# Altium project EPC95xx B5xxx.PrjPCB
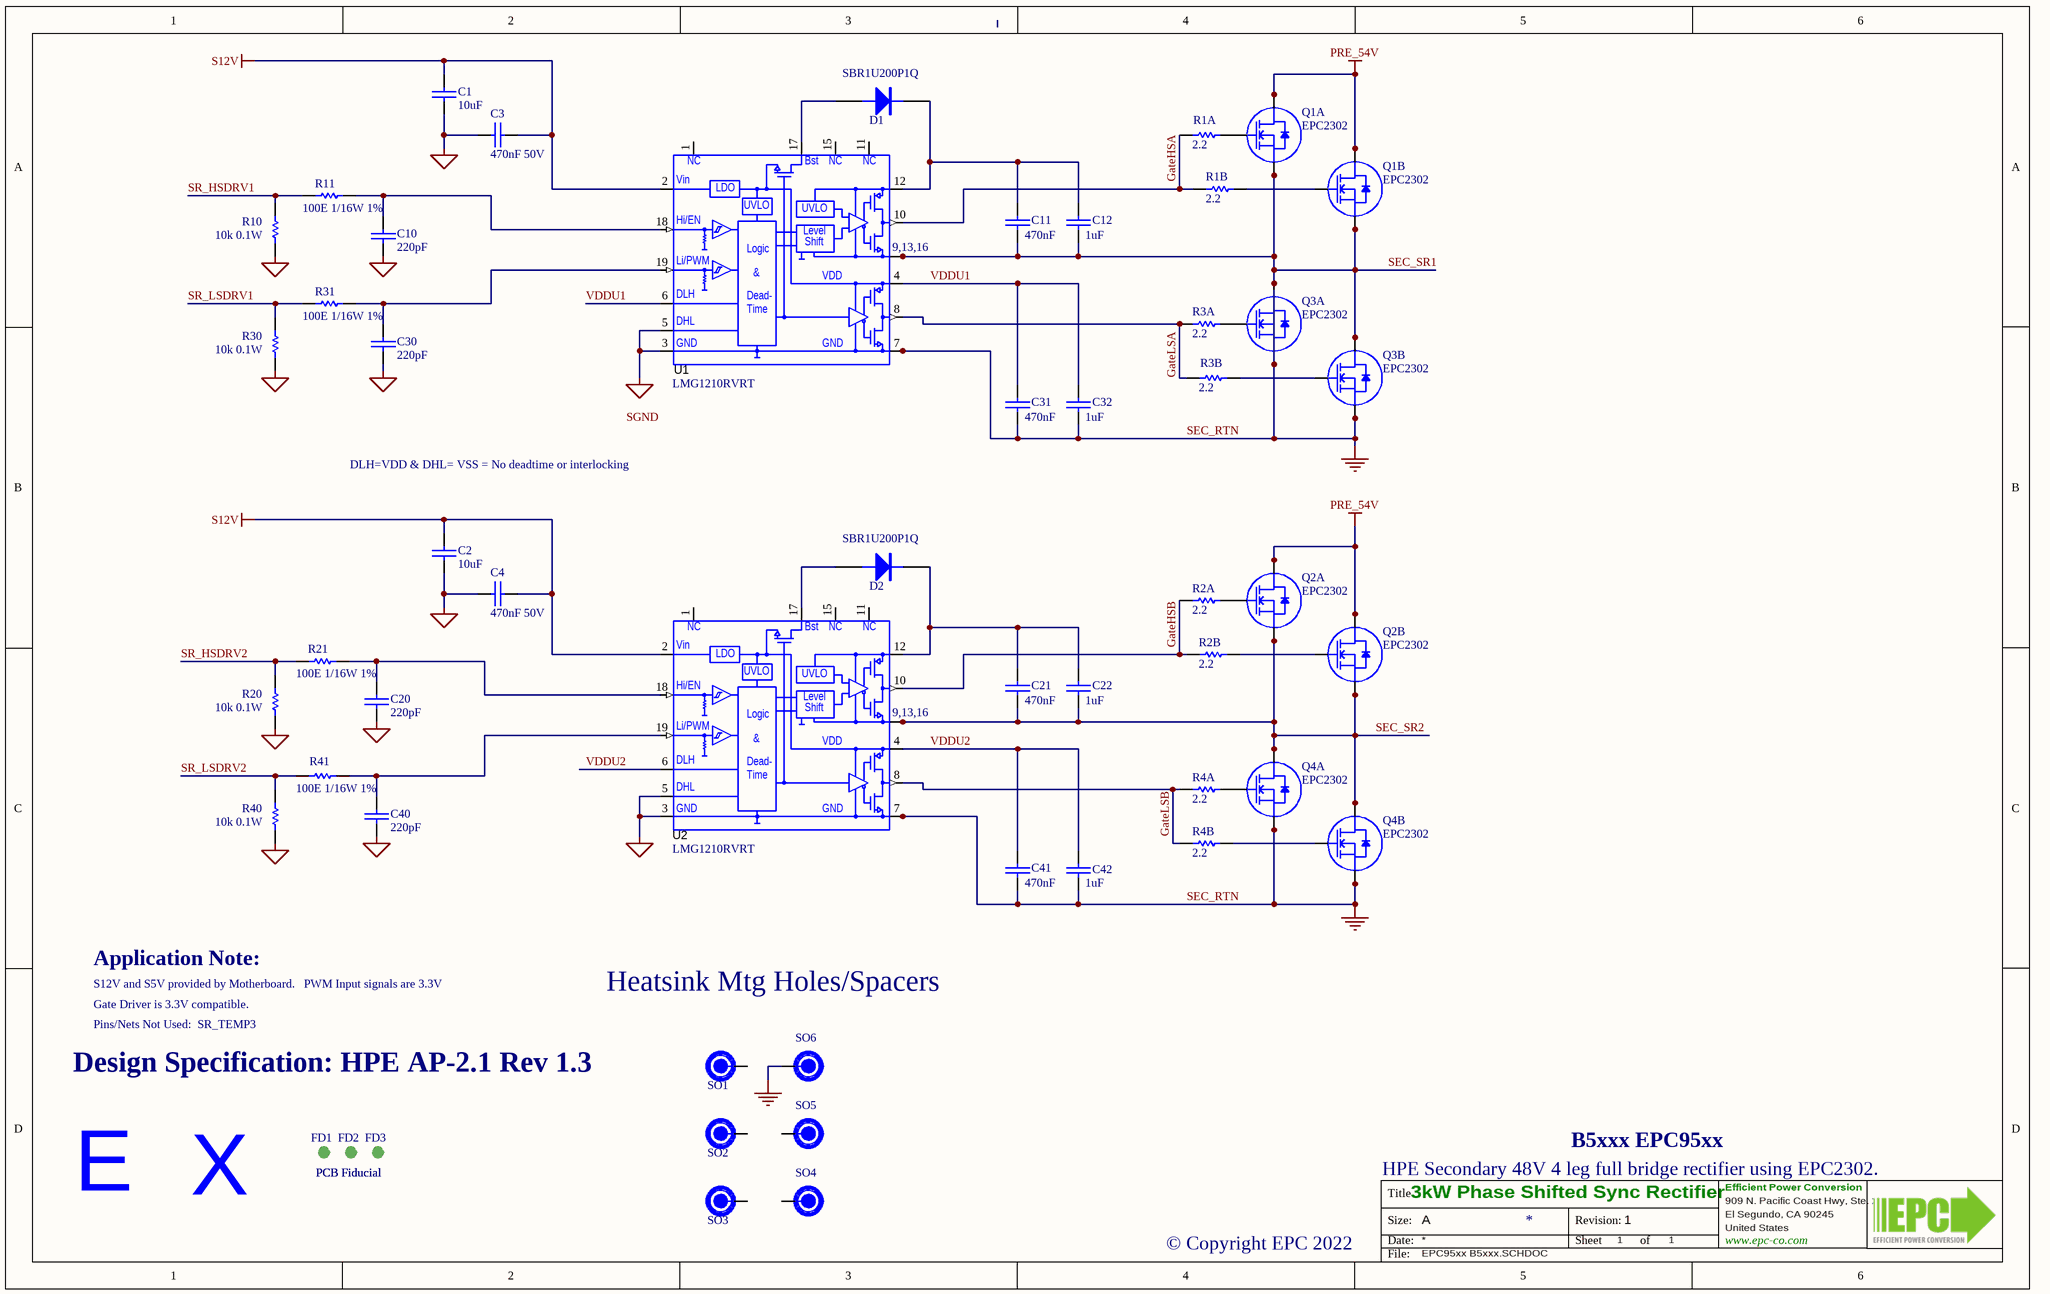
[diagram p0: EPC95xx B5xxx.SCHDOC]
1 sheet, 55 parts. Net scope: global (net labels, ports and power ports of the same name join across sheets).
Board file: EPC95xx B5xxx.PCBDOC

## Sheet EPC95xx B5xxx.SCHDOC: 3kW Phase Shifted Sync Rectifier
size B; Organization: Efficient Power Conversion; Address1: 909 N. Pacific Coast Hwy, Ste. 230; Address2: El Segundo, CA 90245; Address3: United States; Address4: www.epc-co.com; Revision: 1; SheetNumber: 1; SheetTotal: 1

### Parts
C1  value 10uF  [CC0603]  (hidden comment: C1608X5R1E106M080AC)
C2  value 10uF  [CC0603]  (hidden comment: C1608X5R1E106M080AC)
C3  SchDescript: 470nF 50V  [CC0402]  (hidden comment: UMK105ABJ474KV-F)
C4  SchDescript: 470nF 50V  [CC0402]  (hidden comment: UMK105ABJ474KV-F)
C10  value 220pF  [CC0402]  (hidden comment: C1005C0G2A221J050BA)
C11  value 470nF  [CC0402]  (hidden comment: C1005X5R1E474K050BB)
C12  value 1uF  [CC0402]  (hidden comment: C1005X5R1E105K050BC)
C20  value 220pF  [CC0402]  (hidden comment: C1005C0G2A221J050BA)
C21  value 470nF  [CC0402]  (hidden comment: C1005X5R1E474K050BB)
C22  value 1uF  [CC0402]  (hidden comment: C1005X5R1E105K050BC)
C30  value 220pF  [CC0402]  (hidden comment: C1005C0G2A221J050BA)
C31  value 470nF  [CC0402]  (hidden comment: C1005X5R1E474K050BB)
C32  value 1uF  [CC0402]  (hidden comment: C1005X5R1E105K050BC)
C40  value 220pF  [CC0402]  (hidden comment: C1005C0G2A221J050BA)
C41  value 470nF  [CC0402]  (hidden comment: C1005X5R1E474K050BB)
C42  value 1uF  [CC0402]  (hidden comment: C1005X5R1E105K050BC)
D1  SBR1U200P1Q  [PowerDI123]
D2  SBR1U200P1Q  [PowerDI123]
FD1  PCB Fiducial  [Fiducial_Board]  (no BOM)
FD2  PCB Fiducial  [Fiducial_Board]  (no BOM)
FD3  PCB Fiducial  [Fiducial_Board]  (no BOM)
LB2  Hot_SIGN  [Hot_SIGN]  (value not drawn)  (no BOM)
Q1A  EPC2302  [D0606_100V]
Q1B  EPC2302  [D0606_100V]
Q2A  EPC2302  [D0606_100V]
Q2B  EPC2302  [D0606_100V]
Q3A  EPC2302  [D0606_100V]
Q3B  EPC2302  [D0606_100V]
Q4A  EPC2302  [D0606_100V]
Q4B  EPC2302  [D0606_100V]
R1A  value 2.2  [RC0402]  (hidden comment: RMCF0402FT2R0)
R1B  value 2.2  [RC0402]  (hidden comment: RMCF0402FT2R0)
R2A  value 2.2  [RC0402]  (hidden comment: RMCF0402FT2R0)
R2B  value 2.2  [RC0402]  (hidden comment: RMCF0402FT2R0)
R3A  value 2.2  [RC0402]  (hidden comment: RMCF0402FT2R0)
R3B  value 2.2  [RC0402]  (hidden comment: RMCF0402FT2R0)
R4A  value 2.2  [RC0402]  (hidden comment: RMCF0402FT2R0)
R4B  value 2.2  [RC0402]  (hidden comment: RMCF0402FT2R0)
R10  SchDescript: 10k 0.1W  [RC0402]  (hidden comment: ERJ-2RKF1002X)
R11  SchDescript: 100E 1/16W 1%  [RC0402]  (hidden comment: RC0402FR-07100RL)
R20  SchDescript: 10k 0.1W  [RC0402]  (hidden comment: ERJ-2RKF1002X)
R21  SchDescript: 100E 1/16W 1%  [RC0402]  (hidden comment: RC0402FR-07100RL)
R30  SchDescript: 10k 0.1W  [RC0402]  (hidden comment: ERJ-2RKF1002X)
R31  SchDescript: 100E 1/16W 1%  [RC0402]  (hidden comment: RC0402FR-07100RL)
R40  SchDescript: 10k 0.1W  [RC0402]  (hidden comment: ERJ-2RKF1002X)
R41  SchDescript: 100E 1/16W 1%  [RC0402]  (hidden comment: RC0402FR-07100RL)
S2  AntiStat_Sign  [AS_SIGN]  (value not drawn)  (no BOM)
SO1  EPC_Thermal_Spacer_SMD_M2  [9774010243R]  (value not drawn)
SO2  EPC_Thermal_Spacer_SMD_M2  [9774010243R]  (value not drawn)
SO3  EPC_Thermal_Spacer_SMD_M2  [9774010243R]  (value not drawn)
SO4  EPC_Thermal_Spacer_SMD_M2  [9774010243R]  (value not drawn)
SO5  EPC_Thermal_Spacer_SMD_M2  [9774010243R]  (value not drawn)
SO6  EPC_Thermal_Spacer_SMD_M2  [9774010243R]  (value not drawn)
U1  MFGPN: LMG1210RVRT  [WQFN-19]  (hidden comment: LMG1210RVR)
U2  MFGPN: LMG1210RVRT  [WQFN-19]  (hidden comment: LMG1210RVR)

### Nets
PRE_54V: Q1A.3(D) Q1A.5(D) Q1A.7(D) Q1B.3(D) Q1B.5(D) Q1B.7(D) Q2A.3(D) Q2A.5(D) Q2A.7(D) Q2B.3(D) Q2B.5(D) Q2B.7(D)
S12V: C1.2 C2.2 C3.2 C4.2 U1.2(VIN) U2.2(VIN)
SEC_RTN: C31.2 C32.2 C41.2 C42.2 Q3A.2(S) Q3A.4(S) Q3A.6(S) Q3B.2(S) Q3B.4(S) Q3B.6(S) Q4A.2(S) Q4A.4(S) Q4A.6(S) Q4B.2(S) Q4B.4(S) Q4B.6(S) SO6.1 U1.7(GND) U1.20(LS_DAP) U2.7(GND) U2.20(LS_DAP)
SGND: C1.1 C2.1 C3.1 C4.1 C10.2 C20.2 C30.2 C40.2 R10.2 R20.2 R30.2 R40.2 U1.3(GND) U1.5(DHL) U2.3(GND) U2.5(DHL)
GateHSA: R1A.1 R1B.1 U1.10(HO)
GateHSB: R2A.1 R2B.1 U2.10(HO)
GateLSA: R3A.1 R3B.1 U1.8(LO)
GateLSB: R4A.1 R4B.1 U2.8(LO)
SEC_SR1: C11.2 C12.2 Q1A.2(S) Q1A.4(S) Q1A.6(S) Q1B.2(S) Q1B.4(S) Q1B.6(S) Q3A.3(D) Q3A.5(D) Q3A.7(D) Q3B.3(D) Q3B.5(D) Q3B.7(D) U1.9(HS) U1.13(HS) U1.14(NC1) U1.16(HS) U1.21(HS_DAP)
SEC_SR2: C21.2 C22.2 Q2A.2(S) Q2A.4(S) Q2A.6(S) Q2B.2(S) Q2B.4(S) Q2B.6(S) Q4A.3(D) Q4A.5(D) Q4A.7(D) Q4B.3(D) Q4B.5(D) Q4B.7(D) U2.9(HS) U2.13(HS) U2.14(NC1) U2.16(HS) U2.21(HS_DAP)
SR_HSDRV1: R10.1 R11.1
SR_HSDRV2: R20.1 R21.1
SR_LSDRV1: R30.1 R31.1
SR_LSDRV2: R40.1 R41.1
VDDU1: C31.1 C32.1 U1.4(VDD) U1.6(DLH)
VDDU2: C41.1 C42.1 U2.4(VDD) U2.6(DLH)
NetC10_1: C10.1 R11.2 U1.18(HI/EN)
NetC11_1: C11.1 C12.1 D1.2(K) U1.12(HB)
NetC20_1: C20.1 R21.2 U2.18(HI/EN)
NetC21_1: C21.1 C22.1 D2.2(K) U2.12(HB)
NetC30_1: C30.1 R31.2 U1.19(LI/PWM)
NetC40_1: C40.1 R41.2 U2.19(LI/PWM)
NetD1_1: D1.1(A) U1.17(BST)
NetD2_1: D2.1(A) U2.17(BST)
NetQ1A_1: Q1A.1(G) R1A.2
NetQ1B_1: Q1B.1(G) R1B.2
NetQ2A_1: Q2A.1(G) R2A.2
NetQ2B_1: Q2B.1(G) R2B.2
NetQ3A_1: Q3A.1(G) R3A.2
NetQ3B_1: Q3B.1(G) R3B.2
NetQ4A_1: Q4A.1(G) R4A.2
NetQ4B_1: Q4B.1(G) R4B.2

Not connected (* = marked no-connect by the designer): SO1 1; SO2 1; SO3 1; SO4 1; SO5 1; U1 1(NC) 11(NC) 15(NC); U2 1(NC) 11(NC) 15(NC)

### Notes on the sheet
- DLH=VDD & DHL= VSS = No deadtime or interlocking
- Application Note:
- Pins/Nets Not Used:  SR_TEMP3
- Gate Driver is 3.3V compatible.
- S12V and S5V provided by Motherboard.   PWM Input signals are 3.3V
- Heatsink Mtg Holes/Spacers
- Design Specification: HPE AP-2.1 Rev 1.3
- HPE Secondary 48V 4 leg full bridge rectifier using EPC2302.
- B5xxx EPC95xx
- © Copyright EPC 2022
- Labels drawn without touching a wire or pin: SGND

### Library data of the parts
C1 C2 = C0603-10uF-25V-X5R-20%: MFG: TDK; SchDescript: 10uF 25V; QSGdescript: CAP CER 10UF 25V X5R 0603; Voltage: 25; Tolerance: 0.2; Tempco: X5R; Material: Ceramic
C3 C4 = C0402-470nF-50V-X5R-10%: EPC Part Number: C-0402-056; QSGdescript: CAP CER 0.47UF 50V X5R 0402; Value: 470nF; Voltage: 50; Tolerance: 0.1; Tempco: X5R; Material: Ceramic; MFG: Taiyo Yuden
C10 C20 C30 C40 = C0402-220pF-100V-C0G-5%: EPC Part Number: C-0402-040; MFG: TDK; SchDescript: 220pF 100V; QSGdescript: CAP CER 220PF 100V C0G 0402; Voltage: 100; Tolerance: 0.05; Tempco: C0G/NP0; Material: Ceramic
C11 C21 C31 C41 = C0402-470nF-25V-X5R-10%: EPC Part Number: C-0402-054; MFG: TDK; SchDescript: 470nF 25V; QSGdescript: CAP CER 0.47UF 25V X5R 0402; Voltage: 25; Tolerance: 0.1; Tempco: X5R; Material: Ceramic
C12 C22 C32 C42 = C0402-1uF-25V-X5R-10%: EPC Part Number: C-0402-025; MFG: TDK; SchDescript: 1uF 25V; QSGdescript: CAP CER 1UF 25V X5R 0402; Voltage: 25; Tolerance: 0.1; Tempco: X5R; Material: Ceramic
D1 D2 = SBR1U200P1Q: SuperBarrier 200V 1A; MFG: Diodes; Value: 200V 1A
FD1-FD3 = Fiducial_Board: Value: Fiducial 40mil; SchDescript: Fiducial_Board Round Open Round .040
LB2 = Hot_Sign: Hot Symbol
Q1A Q1B Q2A Q2B Q3A Q3B Q4A Q4B = EPC2302: 100V 100A 1.9mE; MFG: EPC; SchDescript: 100V, 1.9mE
R1A R1B R2A R2B R3A R3B R4A R4B = R0402-2.2-1%-1/16W-Thickfilm: EPC Part Number: R-0402-016; Tolerance: 0.01; MFG: Stackpole; SchDescript: 2.2 1/16W; QSGdescript: RES 2.05 OHM 1% 1/16W 0402; Power Rating: 1/16
R10 R20 R30 R40 = R0402-10k-1%-0.1W-Thickfilm: EPC Part Number: R-0402-011; QSGdescript: RES SMD 10K OHM 1% 1/10W 0402; Value: 10k; Power Rating: 0.1; Tolerance: 0.01; MFG: Panasonic
R11 R21 R31 R41 = R0402-100-1%-0.1W-Thickfilm: QSGdescript: RES SMD 100 OHM 1% 1/10W 0402; Value: 100E; Power Rating: 1/16; Tolerance: 0.01; MFG: Yageo
S2 = AntiStat_Sign: Anti-static caution sign; Descript: Anti-Static Symbol
SO1-SO6 = EPC_SMD_Thermal_SpacerM2x1mm: Descript: Round Standoff Threaded M2x0.4 Steel 0.039" (1.00mm); MFG: Wurth; Value: Round Standoff M2x0.4  1.00mm
U1 U2 = LMG1210RVRT: EPC Part Number: IC-109; SchDescript: 300V Half Bridge Gate Driver; Voltage Rating: 300; MFG: Texas Instruments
